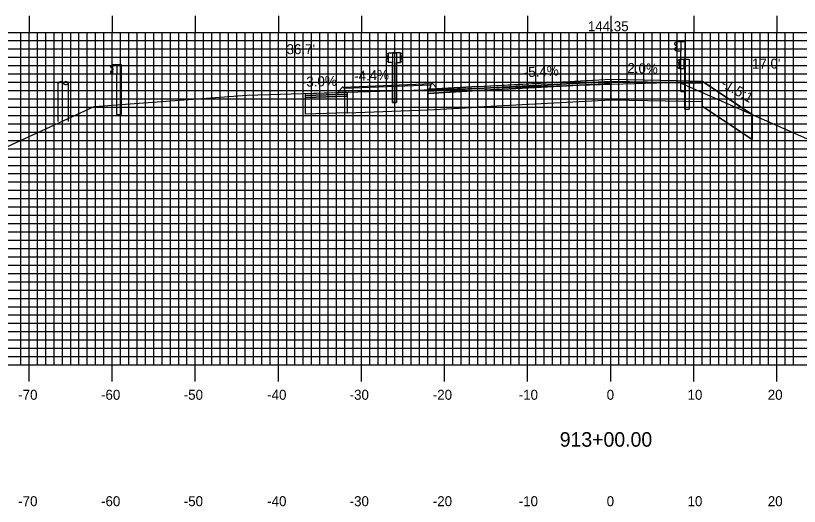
# Model space of a CAD drawing. Extents: x 860258 to 860601, y 364765 to 364985.
# Drawn here: x 860352.3 to 860446.6, y 364836.3 to 364895.3 of the extents above; entities that cross this region are included whole.
import ezdxf

# ---------------------------------------------------------------- set-up
doc = ezdxf.new("R2010")
doc.units = 0
for name, color, linetype in [('ANNOTATION', 7, 'Continuous'), ('D_Curb_Type_3M2_Lt', 7, 'Continuous'), ('D_Curb_Type_3M2_Rt', 7, 'Continuous'), ('D_Guardrail_Beam_Rt', 7, 'Continuous'), ('D_Roadway_Centerline', 7, 'Continuous'), ('D_Roadway_Centerline_Text', 7, 'Continuous'), ('D_Roadway_Edge_Shoulder', 7, 'Continuous'), ('D_Roadway_Edge_TW', 7, 'Continuous'), ('D_Roadway_FinishedGrade', 7, 'Continuous'), ('D_Roadway_Pavement', 7, 'Continuous'), ('D_Roadway_SubGrade', 7, 'Continuous'), ('D_Text_Standard', 7, 'Continuous'), ('H_V ANNOTATION', 7, 'Continuous'), ('M_Guardrail', 7, 'Continuous'), ('M_Roadway_Centerline', 7, 'Continuous'), ('M_Utilities_Pole_StreetLight', 7, 'Continuous'), ('MAJOR', 7, 'Continuous'), ('MINOR', 7, 'Continuous'), ('PATTERNING', 7, 'Continuous'), ('S_Roadway_Centerline', 7, 'Continuous')]:
    doc.layers.add(name, color=color, linetype=linetype)

msp = doc.modelspace()

# ---------------------------------------------------------------- linework, layer by layer
at = {"layer": 'D_Curb_Type_3M2_Lt'}
for p, q in [((860402.257, 364887.012), (860402.149, 364886.518)), ((860402.149, 364886.518), (860402.899, 364886.518)), ((860402.393, 364887.141), (860402.398, 364887.141)), ((860402.899, 364886.685), (860402.545, 364887.087)), ((860402.899, 364886.518), (860402.899, 364886.685))]:
    msp.add_line(p, q, dxfattribs=at)
msp.add_arc((860402.42, 364886.977), 0.167, 41.38705, 167.66476, dxfattribs=at)
at = {"layer": 'D_Curb_Type_3M2_Rt'}
for p, q in [((860391.173, 364886.244), (860391.527, 364886.646)), ((860391.815, 364886.571), (860391.923, 364886.077)), ((860391.173, 364886.077), (860391.173, 364886.244)), ((860391.923, 364886.077), (860391.173, 364886.077))]:
    msp.add_line(p, q, dxfattribs=at)
msp.add_arc((860391.652, 364886.536), 0.167, 12.33524, 138.61295, dxfattribs=at)
at = {"layer": 'D_Guardrail_Beam_Rt'}
for p, q in [((860432.08, 364889.971), (860431.936, 364889.871)), ((860431.936, 364889.728), (860432.132, 364889.592)), ((860432.132, 364889.393), (860431.936, 364889.257)), ((860432.17, 364889.992), (860432.096, 364889.978)), ((860432.166, 364889.527), (860432.166, 364889.457)), ((860432.17, 364890.076), (860432.857, 364890.076)), ((860432.17, 364888.909), (860432.17, 364890.076)), ((860432.691, 364890.076), (860432.691, 364888.909)), ((860432.795, 364890.076), (860432.795, 364888.909)), ((860432.857, 364890.076), (860433.328, 364890.076)), ((860432.857, 364890.076), (860432.857, 364888.909)), ((860433.328, 364890.076), (860433.328, 364884.076)), ((860431.936, 364889.113), (860432.08, 364889.013)), ((860432.096, 364889.007), (860432.17, 364888.992)), ((860432.857, 364888.909), (860432.17, 364888.909)), ((860432.837, 364884.076), (860432.837, 364888.909)), ((860432.837, 364884.076), (860433.328, 364884.076))]:
    msp.add_line(p, q, dxfattribs=at)
for centre, major_axis, start_param, end_param in [((860431.987, 364889.799), (-0.0877, 0), 5.323254, 7.243116), ((860431.987, 364889.185), (-0.0877, 0), 5.323254, 7.243116), ((860432.104, 364889.937), (-0.0417, 0), 4.907132, 5.323254), ((860432.087, 364889.527), (0.0789, 0), 0, 0.959931), ((860432.087, 364889.457), (0.0789, 0), 5.323254, 6.283185), ((860432.104, 364889.047), (-0.0417, 0), 0.959931, 1.376053)]:
    msp.add_ellipse(centre, major_axis=major_axis, ratio=0.995501, start_param=start_param, end_param=end_param, dxfattribs=at)
at = {"layer": 'D_Roadway_Centerline'}
for points in [[(860402.9, 364886.518), (860407.899, 364886.788), (860412.643, 364887.044), (860423.891, 364887.652), (860423.899, 364887.652), (860431.893, 364887.492), (860431.899, 364887.492), (860434.899, 364887.432), (860440.944, 364883.402)], [(860387.173, 364885.958), (860391.171, 364886.077)]]:
    msp.add_lwpolyline(points, dxfattribs=at)
at = {"layer": 'D_Roadway_Edge_Shoulder'}
for points in [[(860423.899, 364887.652), (860431.899, 364887.492), (860431.899, 364887.492), (860434.899, 364887.432), (860434.899, 364887.182), (860423.899, 364887.402)], [(860407.899, 364886.788), (860402.899, 364886.518), (860401.899, 364886.464), (860401.899, 364886.214), (860407.899, 364886.538)], [(860387.173, 364885.958), (860391.173, 364886.077), (860392.173, 364886.107), (860392.173, 364885.857), (860387.173, 364885.708)]]:
    msp.add_lwpolyline(points, close=True, dxfattribs=at)
at = {"layer": 'D_Roadway_Edge_TW'}
msp.add_lwpolyline([(860407.899, 364886.788), (860423.899, 364887.652), (860423.899, 364887.402), (860407.899, 364886.538)], close=True, dxfattribs=at)
at = {"layer": 'D_Roadway_FinishedGrade'}
for q in [(860436.399, 364886.432), (860434.899, 364884.432)]:
    msp.add_line((860434.899, 364887.432), q, dxfattribs=at)
for points in [[(860434.899, 364887.432), (860436.399, 364886.432), (860440.944, 364883.402)], [(860391.694, 364886.697), (860402.378, 364887.138)], [(860440.944, 364883.402), (860440.944, 364880.402), (860434.899, 364884.432)]]:
    msp.add_lwpolyline(points, dxfattribs=at)
at = {"layer": 'D_Roadway_Pavement'}
for points in [[(860407.899, 364886.538), (860423.899, 364887.402), (860423.899, 364887.152), (860407.899, 364886.288)], [(860407.899, 364886.538), (860401.899, 364886.214), (860401.899, 364885.964), (860407.899, 364886.288)], [(860387.173, 364885.708), (860392.173, 364885.857), (860392.173, 364885.607), (860387.173, 364885.458)]]:
    msp.add_lwpolyline(points, close=True, dxfattribs=at)
msp.add_lwpolyline([(860423.899, 364887.402), (860423.899, 364887.152)], dxfattribs=at)
msp.add_lwpolyline([(860423.899, 364887.402), (860423.899, 364887.152)], dxfattribs=at)
at = {"layer": 'D_Roadway_SubGrade'}
for points in [[(860423.899, 364887.152), (860423.899, 364887.402), (860434.899, 364887.182), (860434.899, 364887.432), (860434.899, 364884.932), (860423.899, 364885.152)], [(860392.173, 364886.107), (860392.173, 364883.607), (860401.899, 364883.964), (860401.899, 364885.964), (860401.899, 364886.214), (860401.899, 364886.464), (860402.14, 364886.477), (860402.247, 364886.966), (860391.823, 364886.535), (860391.918, 364886.1)], [(860407.899, 364886.288), (860423.899, 364887.152), (860423.899, 364885.152), (860407.899, 364884.288)], [(860387.173, 364885.458), (860392.173, 364885.607), (860392.173, 364885.857), (860392.173, 364883.607), (860387.173, 364883.458)], [(860407.899, 364886.288), (860401.899, 364885.964), (860401.899, 364886.214), (860401.899, 364883.964), (860407.899, 364884.288)]]:
    msp.add_lwpolyline(points, close=True, dxfattribs=at)
at = {"layer": 'M_Guardrail'}
for p, q in [((860431.754, 364892.092), (860431.61, 364891.992)), ((860431.852, 364892.114), (860431.77, 364892.099)), ((860431.852, 364892.187), (860432.342, 364892.187)), ((860431.852, 364891.02), (860431.852, 364892.187)), ((860432.342, 364892.187), (860432.834, 364892.187)), ((860432.342, 364892.187), (860432.342, 364891.02)), ((860432.834, 364892.187), (860432.834, 364886.187)), ((860431.61, 364891.849), (860431.806, 364891.713)), ((860431.806, 364891.493), (860431.61, 364891.357)), ((860431.61, 364891.214), (860431.754, 364891.114)), ((860431.77, 364891.107), (860431.852, 364891.093)), ((860431.839, 364891.649), (860431.839, 364891.558)), ((860397.057, 364890.756), (860396.914, 364890.656)), ((860396.914, 364890.513), (860397.109, 364890.377)), ((860397.109, 364890.157), (860396.914, 364890.021)), ((860397.156, 364890.777), (860397.074, 364890.763)), ((860397.143, 364890.312), (860397.143, 364890.221)), ((860397.156, 364890.85), (860397.646, 364890.85)), ((860397.156, 364889.684), (860397.156, 364890.85)), ((860397.633, 364890.85), (860397.633, 364884.85)), ((860398.125, 364890.85), (860397.633, 364890.85)), ((860397.646, 364890.85), (860398.137, 364890.85)), ((860397.646, 364890.85), (860397.646, 364889.684)), ((860398.614, 364890.85), (860398.125, 364890.85)), ((860398.125, 364890.85), (860398.125, 364889.684)), ((860398.137, 364890.85), (860398.137, 364884.85)), ((860398.614, 364889.684), (860398.614, 364890.85)), ((860398.614, 364890.778), (860398.697, 364890.763)), ((860398.628, 364890.313), (860398.628, 364890.222)), ((860398.857, 364890.513), (860398.661, 364890.377)), ((860398.661, 364890.157), (860398.857, 364890.021)), ((860398.713, 364890.756), (860398.857, 364890.656)), ((860432.342, 364891.02), (860431.852, 364891.02)), ((860432.342, 364886.187), (860432.342, 364891.02)), ((860363.881, 364889.337), (860363.737, 364889.237)), ((860363.98, 364889.358), (860363.897, 364889.343)), ((860363.98, 364889.431), (860364.469, 364889.431)), ((860363.98, 364888.264), (860363.98, 364889.431)), ((860364.469, 364889.431), (860364.961, 364889.431)), ((860364.469, 364889.431), (860364.469, 364888.264)), ((860364.961, 364889.431), (860364.961, 364883.431)), ((860396.914, 364889.878), (860397.057, 364889.778)), ((860397.074, 364889.771), (860397.156, 364889.756)), ((860397.646, 364889.684), (860397.156, 364889.684)), ((860397.646, 364884.85), (860397.646, 364889.684)), ((860398.125, 364884.85), (860398.125, 364889.684)), ((860398.125, 364889.684), (860398.614, 364889.684)), ((860398.697, 364889.771), (860398.614, 364889.757)), ((860398.857, 364889.878), (860398.713, 364889.778)), ((860363.737, 364889.094), (860363.933, 364888.957)), ((860363.933, 364888.738), (860363.737, 364888.601)), ((860363.737, 364888.458), (860363.881, 364888.358)), ((860363.897, 364888.351), (860363.98, 364888.337)), ((860363.966, 364888.893), (860363.966, 364888.802)), ((860364.469, 364888.264), (860363.98, 364888.264)), ((860364.469, 364883.431), (860364.469, 364888.264)), ((860432.342, 364886.187), (860432.834, 364886.187)), ((860398.125, 364884.85), (860397.633, 364884.85)), ((860397.646, 364884.85), (860398.137, 364884.85)), ((860364.469, 364883.431), (860364.961, 364883.431))]:
    msp.add_line(p, q, dxfattribs=at)
for centre, major_axis, start_param, end_param in [((860431.661, 364891.921), (-0.0877, 0), 5.323254, 7.243116), ((860431.778, 364892.058), (-0.0417, 0), 4.886922, 5.323254), ((860431.661, 364891.286), (-0.0877, 0), 5.323254, 7.243116), ((860431.778, 364891.148), (-0.0417, 0), 0.959931, 1.396263), ((860431.76, 364891.649), (0.0789, 0), 0, 0.959931), ((860431.76, 364891.558), (0.0789, 0), 5.323254, 6.283185), ((860396.964, 364890.584), (-0.0877, 0), 5.323254, 7.243116), ((860397.081, 364890.722), (-0.0417, 0), 4.886922, 5.323254), ((860397.064, 364890.312), (0.0789, 0), 0, 0.959931), ((860397.064, 364890.221), (0.0789, 0), 5.323254, 6.283185), ((860398.707, 364890.313), (-0.0789, 0), 5.323254, 6.283185), ((860398.707, 364890.222), (-0.0789, 0), 6.283185, 7.243116), ((860398.689, 364890.722), (0.0417, 0), 0.959931, 1.396263), ((860398.806, 364890.585), (0.0877, 0), 5.323254, 7.243116), ((860363.788, 364889.165), (-0.0877, 0), 5.323254, 7.243116), ((860363.905, 364889.303), (-0.0417, 0), 4.886922, 5.323254), ((860396.964, 364889.949), (-0.0877, 0), 5.323254, 7.243116), ((860397.081, 364889.812), (-0.0417, 0), 0.959931, 1.396263), ((860398.689, 364889.812), (0.0417, 0), 4.886922, 5.323254), ((860398.806, 364889.949), (0.0877, 0), 5.323254, 7.243116), ((860363.788, 364888.53), (-0.0877, 0), 5.323254, 7.243116), ((860363.905, 364888.392), (-0.0417, 0), 0.959931, 1.396263), ((860363.887, 364888.893), (0.0789, 0), 0, 0.959931), ((860363.887, 364888.802), (0.0789, 0), 5.323254, 6.283185)]:
    msp.add_ellipse(centre, major_axis=major_axis, ratio=0.995501, start_param=start_param, end_param=end_param, dxfattribs=at)
at = {"layer": 'M_Utilities_Pole_StreetLight'}
for p, q in [((860357.38, 364887.181), (860357.536, 364887.292)), ((860357.848, 364887.292), (860358.004, 364887.181)), ((860358.161, 364887.292), (860358.004, 364887.181)), ((860358.63, 364887.181), (860358.474, 364887.292)), ((860357.38, 364882.562), (860357.377, 364887.181)), ((860358.004, 364887.181), (860358.161, 364887.07)), ((860358.474, 364887.07), (860358.63, 364887.181)), ((860358.63, 364882.562), (860358.627, 364887.181))]:
    msp.add_line(p, q, dxfattribs=at)
for centre, start, end in [((860357.692, 364887.071), 90, 125.26439), ((860357.692, 364887.071), 54.73561, 90), ((860358.317, 364887.071), 90, 125.26439), ((860358.317, 364887.071), 54.73561, 90), ((860358.317, 364887.292), 234.73561, 270), ((860358.317, 364887.292), 270, 305.26439)]:
    msp.add_arc(centre, 0.271, start, end, dxfattribs=at)
at = {"layer": 'MAJOR'}
for p, q in [((860353.899, 364895.306), (860353.899, 364893.302)), ((860363.899, 364895.306), (860363.899, 364893.302)), ((860373.899, 364895.306), (860373.899, 364893.302)), ((860383.899, 364895.306), (860383.899, 364893.302)), ((860393.899, 364895.306), (860393.899, 364893.302)), ((860403.899, 364895.306), (860403.899, 364893.302)), ((860413.899, 364895.306), (860413.899, 364893.302)), ((860423.899, 364895.306), (860423.899, 364893.302)), ((860433.899, 364895.306), (860433.899, 364893.302)), ((860443.899, 364895.306), (860443.899, 364893.302)), ((860283.899, 364893.302), (860563.899, 364893.302)), ((860283.899, 364893.302), (860563.899, 364893.302)), ((860353.899, 364853.302), (860353.899, 364893.302)), ((860363.899, 364853.302), (860363.899, 364893.302)), ((860373.899, 364853.302), (860373.899, 364893.302)), ((860383.899, 364853.302), (860383.899, 364893.302)), ((860393.899, 364853.302), (860393.899, 364893.302)), ((860403.899, 364853.302), (860403.899, 364893.302)), ((860413.899, 364853.302), (860413.899, 364893.302)), ((860423.899, 364853.302), (860423.899, 364893.302)), ((860433.899, 364853.302), (860433.899, 364893.302)), ((860443.899, 364853.302), (860443.899, 364893.302)), ((860283.899, 364888.302), (860563.899, 364888.302)), ((860283.899, 364883.302), (860563.899, 364883.302)), ((860283.899, 364878.302), (860563.899, 364878.302)), ((860283.899, 364873.302), (860563.899, 364873.302)), ((860283.899, 364868.302), (860563.899, 364868.302)), ((860283.899, 364863.302), (860563.899, 364863.302)), ((860283.899, 364858.302), (860563.899, 364858.302)), ((860283.899, 364853.302), (860563.899, 364853.302)), ((860283.899, 364853.302), (860563.899, 364853.302)), ((860353.899, 364851.298), (860353.899, 364853.302)), ((860363.899, 364851.298), (860363.899, 364853.302)), ((860373.899, 364851.298), (860373.899, 364853.302)), ((860383.899, 364851.298), (860383.899, 364853.302)), ((860393.899, 364851.298), (860393.899, 364853.302)), ((860403.899, 364851.298), (860403.899, 364853.302)), ((860413.899, 364851.298), (860413.899, 364853.302)), ((860423.899, 364851.298), (860423.899, 364853.302)), ((860433.899, 364851.298), (860433.899, 364853.302)), ((860443.899, 364851.298), (860443.899, 364853.302))]:
    msp.add_line(p, q, dxfattribs=at)
at = {"layer": 'MINOR'}
for p, q in [((860352.899, 364853.302), (860352.899, 364893.302)), ((860354.899, 364853.302), (860354.899, 364893.302)), ((860355.899, 364853.302), (860355.899, 364893.302)), ((860356.899, 364853.302), (860356.899, 364893.302)), ((860357.899, 364853.302), (860357.899, 364893.302)), ((860358.899, 364853.302), (860358.899, 364893.302)), ((860359.899, 364853.302), (860359.899, 364893.302)), ((860360.899, 364853.302), (860360.899, 364893.302)), ((860361.899, 364853.302), (860361.899, 364893.302)), ((860362.899, 364853.302), (860362.899, 364893.302)), ((860364.899, 364853.302), (860364.899, 364893.302)), ((860365.899, 364853.302), (860365.899, 364893.302)), ((860366.899, 364853.302), (860366.899, 364893.302)), ((860367.899, 364853.302), (860367.899, 364893.302)), ((860368.899, 364853.302), (860368.899, 364893.302)), ((860369.899, 364853.302), (860369.899, 364893.302)), ((860370.899, 364853.302), (860370.899, 364893.302)), ((860371.899, 364853.302), (860371.899, 364893.302)), ((860372.899, 364853.302), (860372.899, 364893.302)), ((860374.899, 364853.302), (860374.899, 364893.302)), ((860375.899, 364853.302), (860375.899, 364893.302)), ((860376.899, 364853.302), (860376.899, 364893.302)), ((860377.899, 364853.302), (860377.899, 364893.302)), ((860378.899, 364853.302), (860378.899, 364893.302)), ((860379.899, 364853.302), (860379.899, 364893.302)), ((860380.899, 364853.302), (860380.899, 364893.302)), ((860381.899, 364853.302), (860381.899, 364893.302)), ((860382.899, 364853.302), (860382.899, 364893.302)), ((860384.899, 364853.302), (860384.899, 364893.302)), ((860385.899, 364853.302), (860385.899, 364893.302)), ((860386.899, 364853.302), (860386.899, 364893.302)), ((860387.899, 364853.302), (860387.899, 364893.302)), ((860388.899, 364853.302), (860388.899, 364893.302)), ((860389.899, 364853.302), (860389.899, 364893.302)), ((860390.899, 364853.302), (860390.899, 364893.302)), ((860391.899, 364853.302), (860391.899, 364893.302)), ((860392.899, 364853.302), (860392.899, 364893.302)), ((860394.899, 364853.302), (860394.899, 364893.302)), ((860395.899, 364853.302), (860395.899, 364893.302)), ((860396.899, 364853.302), (860396.899, 364893.302)), ((860397.899, 364853.302), (860397.899, 364893.302)), ((860398.899, 364853.302), (860398.899, 364893.302)), ((860399.899, 364853.302), (860399.899, 364893.302)), ((860400.899, 364853.302), (860400.899, 364893.302)), ((860401.899, 364853.302), (860401.899, 364893.302)), ((860402.899, 364853.302), (860402.899, 364893.302)), ((860404.899, 364853.302), (860404.899, 364893.302)), ((860405.899, 364853.302), (860405.899, 364893.302)), ((860406.899, 364853.302), (860406.899, 364893.302)), ((860407.899, 364853.302), (860407.899, 364893.302)), ((860408.899, 364853.302), (860408.899, 364893.302)), ((860409.899, 364853.302), (860409.899, 364893.302)), ((860410.899, 364853.302), (860410.899, 364893.302)), ((860411.899, 364853.302), (860411.899, 364893.302)), ((860412.899, 364853.302), (860412.899, 364893.302)), ((860414.899, 364853.302), (860414.899, 364893.302)), ((860415.899, 364853.302), (860415.899, 364893.302)), ((860416.899, 364853.302), (860416.899, 364893.302)), ((860417.899, 364853.302), (860417.899, 364893.302)), ((860418.899, 364853.302), (860418.899, 364893.302)), ((860419.899, 364853.302), (860419.899, 364893.302)), ((860420.899, 364853.302), (860420.899, 364893.302)), ((860421.899, 364853.302), (860421.899, 364893.302)), ((860422.899, 364853.302), (860422.899, 364893.302)), ((860424.899, 364853.302), (860424.899, 364893.302)), ((860425.899, 364853.302), (860425.899, 364893.302)), ((860426.899, 364853.302), (860426.899, 364893.302)), ((860427.899, 364853.302), (860427.899, 364893.302)), ((860428.899, 364853.302), (860428.899, 364893.302)), ((860429.899, 364853.302), (860429.899, 364893.302)), ((860430.899, 364853.302), (860430.899, 364893.302)), ((860431.899, 364853.302), (860431.899, 364893.302)), ((860432.899, 364853.302), (860432.899, 364893.302)), ((860434.899, 364853.302), (860434.899, 364893.302)), ((860435.899, 364853.302), (860435.899, 364893.302)), ((860436.899, 364853.302), (860436.899, 364893.302)), ((860437.899, 364853.302), (860437.899, 364893.302)), ((860438.899, 364853.302), (860438.899, 364893.302)), ((860439.899, 364853.302), (860439.899, 364893.302)), ((860440.899, 364853.302), (860440.899, 364893.302)), ((860441.899, 364853.302), (860441.899, 364893.302)), ((860442.899, 364853.302), (860442.899, 364893.302)), ((860444.899, 364853.302), (860444.899, 364893.302)), ((860445.899, 364853.302), (860445.899, 364893.302)), ((860283.899, 364892.302), (860563.899, 364892.302)), ((860283.899, 364891.302), (860563.899, 364891.302)), ((860283.899, 364890.302), (860563.899, 364890.302)), ((860283.899, 364889.302), (860563.899, 364889.302)), ((860283.899, 364887.302), (860563.899, 364887.302)), ((860283.899, 364886.302), (860563.899, 364886.302)), ((860283.899, 364885.302), (860563.899, 364885.302)), ((860283.899, 364884.302), (860563.899, 364884.302)), ((860283.899, 364882.302), (860563.899, 364882.302)), ((860283.899, 364881.302), (860563.899, 364881.302)), ((860283.899, 364880.302), (860563.899, 364880.302)), ((860283.899, 364879.302), (860563.899, 364879.302)), ((860283.899, 364877.302), (860563.899, 364877.302)), ((860283.899, 364876.302), (860563.899, 364876.302)), ((860283.899, 364875.302), (860563.899, 364875.302)), ((860283.899, 364874.302), (860563.899, 364874.302)), ((860283.899, 364872.302), (860563.899, 364872.302)), ((860283.899, 364871.302), (860563.899, 364871.302)), ((860283.899, 364870.302), (860563.899, 364870.302)), ((860283.899, 364869.302), (860563.899, 364869.302)), ((860283.899, 364867.302), (860563.899, 364867.302)), ((860283.899, 364866.302), (860563.899, 364866.302)), ((860283.899, 364865.302), (860563.899, 364865.302)), ((860283.899, 364864.302), (860563.899, 364864.302)), ((860283.899, 364862.302), (860563.899, 364862.302)), ((860283.899, 364861.302), (860563.899, 364861.302)), ((860283.899, 364860.302), (860563.899, 364860.302)), ((860283.899, 364859.302), (860563.899, 364859.302)), ((860283.899, 364857.302), (860563.899, 364857.302)), ((860283.899, 364856.302), (860563.899, 364856.302)), ((860283.899, 364855.302), (860563.899, 364855.302)), ((860283.899, 364854.302), (860563.899, 364854.302))]:
    msp.add_line(p, q, dxfattribs=at)
at = {"layer": 'PATTERNING'}
for p, q in [((860434.899, 364887.432), (860434.899, 364887.182)), ((860434.899, 364887.182), (860434.899, 364884.932)), ((860434.899, 364884.932), (860434.899, 364884.432))]:
    msp.add_line(p, q, dxfattribs=at)
for points in [[(860440.944, 364883.402), (860436.399, 364886.432), (860434.899, 364887.432)], [(860434.899, 364884.932), (860434.899, 364884.932)], [(860434.899, 364884.432), (860440.944, 364880.402), (860440.944, 364883.402)]]:
    msp.add_lwpolyline(points, dxfattribs=at)
at = {"layer": 'S_Roadway_Centerline'}
msp.add_lwpolyline([(860283.899, 364859.669), (860290.091, 364860.008), (860302.076, 364861.181), (860305.082, 364861.319), (860318.331, 364864.994), (860321.463, 364865.709), (860333.426, 364871.361), (860361.715, 364884.397), (860363.878, 364884.537), (860380.096, 364885.746), (860404.193, 364886.467), (860411.742, 364886.709), (860418.649, 364886.906), (860432.089, 364887.303), (860483.015, 364864.869)], dxfattribs=at)

# ---------------------------------------------------------------- texts
at = {"layer": 'ANNOTATION'}
for s, rotation, p in [('-5.4%', 3.09097, (860413.479, 364887.892)), ('2.0%', 358.85414, (860425.903, 364888.413)), ('-4.4%', 2.49646, (860393.042, 364887.446)), ('-3.0%', 1.71068, (860386.748, 364886.746)), ('-1.5:1', 330.177, (860437.072, 364886.819))]:
    msp.add_text(s, height=1.2, rotation=rotation, dxfattribs=at).set_placement(p)
at = {"layer": 'D_Roadway_Centerline_Text'}
msp.add_text('144.35', height=1.2, dxfattribs=at).set_placement((860421.154, 364893.439))
at = {"layer": 'D_Text_Standard'}
for s, p in [("36.7'", (860384.885, 364890.677)), ("17.0'", (860440.909, 364888.942))]:
    msp.add_text(s, height=1.2, dxfattribs=at).set_placement(p)
at = {"layer": 'H_V ANNOTATION'}
for s, height, p in [('-70', 1.2, (860352.583, 364849.102)), ('-60', 1.2, (860362.551, 364849.102)), ('-50', 1.2, (860372.508, 364849.102)), ('-40', 1.2, (860382.551, 364849.102)), ('-30', 1.2, (860392.476, 364849.102)), ('-20', 1.2, (860402.486, 364849.102)), ('-10', 1.2, (860412.829, 364849.102)), ('0', 1.2, (860423.417, 364849.102)), ('10', 1.2, (860433.15, 364849.102)), ('20', 1.2, (860442.807, 364849.102)), ('913+00.00', 1.75, (860417.766, 364843.458)), ('-70', 1.2, (860352.583, 364836.302)), ('-60', 1.2, (860362.551, 364836.302)), ('-50', 1.2, (860372.508, 364836.302)), ('-40', 1.2, (860382.551, 364836.302)), ('-30', 1.2, (860392.476, 364836.302)), ('-20', 1.2, (860402.486, 364836.302)), ('-10', 1.2, (860412.829, 364836.302)), ('0', 1.2, (860423.417, 364836.302)), ('10', 1.2, (860433.15, 364836.302)), ('20', 1.2, (860442.807, 364836.302))]:
    msp.add_text(s, height=height, dxfattribs=at).set_placement(p)
at = {"layer": 'M_Roadway_Centerline'}
for s, p in [('C', (860411.737, 364886.709)), ('L', (860411.742, 364886.702)), ('C', (860380.091, 364885.746)), ('L', (860380.096, 364885.739))]:
    msp.add_text(s, height=0.0146, dxfattribs=at).set_placement(p)

doc.saveas('drawing.dxf')
